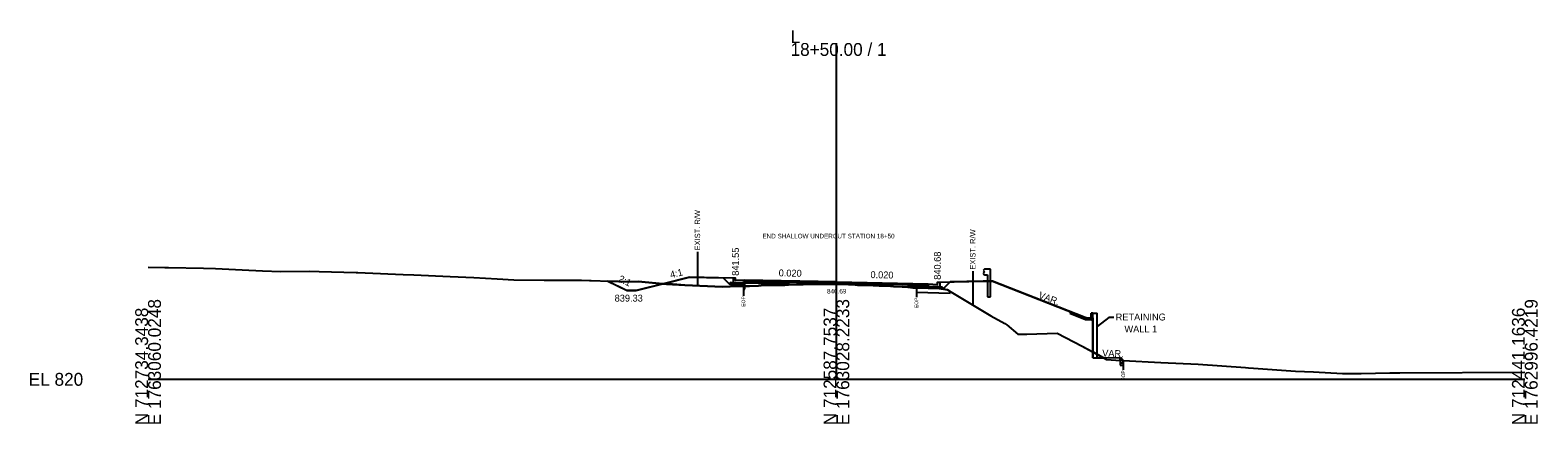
# Model space of a CAD drawing. Extents: x -26 to 5303, y -10 to 9578.
# Drawn here: x -25.7 to 302.8, y 8490.3 to 8576 of the extents above; entities that cross this region are included whole.
import ezdxf

# ---------------------------------------------------------------- set-up
doc = ezdxf.new("R2010")
doc.units = 0
for name, color, linetype in [('Default', 7, 'Continuous'), ('Exist CMT Pavement', 7, 'Continuous'), ('Exist Cross Section Cell', 7, 'Continuous'), ('Exist XS Ground Line', 7, 'Continuous'), ('Old_Level_10', 7, 'Continuous'), ('Old_Level_3', 7, 'Continuous'), ('Old_Level_4', 7, 'Continuous'), ('Prop CMT Conc Surface', 7, 'Continuous'), ('Prop CMT Concrete Structures', 7, 'Continuous'), ('Prop CMT Guardrail Graphics', 7, 'Continuous'), ('Prop CMT Pvmt Course 1', 7, 'Continuous'), ('Prop CMT Pvmt Course 1 CG', 7, 'Continuous'), ('Prop CMT Pvmt Course 2', 7, 'Continuous'), ('Prop CMT Pvmt Course 3', 7, 'Continuous'), ('Prop CMT Pvmt Surface', 7, 'Continuous'), ('Prop CMT Slope Grass', 7, 'Continuous'), ('Prop CMT Subgrade Earthwork', 7, 'Continuous'), ('Prop Retaining Wall', 7, 'Continuous'), ('Prop Shade Light', 7, 'Continuous'), ('Prop XS DDE', 7, 'Continuous'), ('Prop XS DDE Earthwork Shape', 7, 'Continuous'), ('Prop XS Earthwork Shape', 7, 'Continuous'), ('Prop XS Hydro Elevations', 7, 'Continuous'), ('Prop XS Hydro Slope Text', 7, 'Continuous'), ('Prop XS SBG', 7, 'Continuous'), ('Prop XS SE Text', 7, 'Continuous'), ('Prop XS Side Slope Text', 7, 'Continuous'), ('Prop XS Wedging', 7, 'Continuous'), ('Typical Curb CELL', 7, 'Continuous')]:
    doc.layers.add(name, color=color, linetype=linetype)

msp = doc.modelspace()

# ---------------------------------------------------------------- linework, layer by layer
at = {"layer": 'Exist CMT Pavement'}
msp.add_lwpolyline([(130, 8520.26), (130.74, 8520.3), (131.07, 8520.32), (133.05, 8520.39), (133.63, 8520.41), (135.72, 8520.48), (136.32, 8520.5), (138.75, 8520.54), (139.59, 8520.57), (141.31, 8520.62), (142.04, 8520.65), (142.78, 8520.67), (143.65, 8520.71), (144.12, 8520.72), (144.91, 8520.74), (145.38, 8520.73), (146.42, 8520.75), (147.52, 8520.73), (148.98, 8520.7), (149.39, 8520.69), (150, 8520.69), (151.54, 8520.69), (152.92, 8520.63), (154.1, 8520.56), (154.59, 8520.53), (155.22, 8520.51), (155.73, 8520.51), (156.15, 8520.48), (156.65, 8520.47), (159.31, 8520.38), (161.77, 8520.27), (162.45, 8520.23), (164.33, 8520.15), (165.54, 8520.06), (166.15, 8520.02), (166.63, 8519.96), (167.42, 8519.95)], dxfattribs=at)
at = {"layer": 'Exist Cross Section Cell'}
for p, q in [((150, 8500), (150, 8573.24)), ((0, 8500), (150, 8500)), ((150, 8500), (300, 8500))]:
    msp.add_line(p, q, dxfattribs=at)
at = {"layer": 'Exist XS Ground Line'}
msp.add_lwpolyline([(0, 8524.41), (3.67, 8524.36), (4.44, 8524.36), (12.08, 8524.19), (14.68, 8524.11), (20.49, 8523.81), (24.91, 8523.62), (28.9, 8523.49), (35.14, 8523.52), (37.31, 8523.45), (45.38, 8523.26), (45.72, 8523.25), (47.28, 8523.22), (55.61, 8522.86), (57.91, 8522.76), (65.84, 8522.39), (70.98, 8522.2), (76.07, 8521.92), (79.71, 8521.68), (86.34, 8521.62), (94.45, 8521.57), (96.17, 8521.54), (96.54, 8521.53), (104.57, 8521.26), (106.77, 8521.27), (112.98, 8520.7), (117, 8520.5), (121.9, 8520.28), (125.13, 8520.15), (128.64, 8520.28), (129.73, 8520.25), (130.74, 8520.3), (131.07, 8520.32), (131.9, 8520.35), (133.63, 8520.41), (135.72, 8520.48), (136.32, 8520.5), (138.75, 8520.54), (139.59, 8520.57), (141.31, 8520.62), (141.91, 8520.65), (142.72, 8520.67), (143.65, 8520.71), (144.15, 8520.72), (144.91, 8520.74), (145.38, 8520.73), (146.42, 8520.75), (147.52, 8520.73), (148.98, 8520.7), (149.39, 8520.69), (150, 8520.69), (151.54, 8520.69), (152.65, 8520.63), (154.21, 8520.58), (155.32, 8520.53), (155.73, 8520.51), (156.15, 8520.48), (156.65, 8520.47), (159.31, 8520.38), (161.77, 8520.27), (162.45, 8520.23), (164.33, 8520.15), (165.54, 8520.06), (166.15, 8520.02), (166.63, 8519.96), (167.42, 8519.95), (167.89, 8520.03), (172.4, 8519.75), (174.22, 8519.46), (183.62, 8513.84), (186.73, 8512.13), (187.14, 8511.86), (189.53, 8509.84), (191.51, 8509.87), (198.12, 8510.02), (203.57, 8507.24), (208.87, 8504.32), (210.86, 8504.17), (212.51, 8504.1), (220.69, 8503.69), (228.8, 8503.3), (239.16, 8502.54), (239.79, 8502.48), (240.86, 8502.41), (250.03, 8501.76), (253.93, 8501.61), (260.26, 8501.28), (263.46, 8501.3), (264.34, 8501.29), (270.62, 8501.44), (272.74, 8501.44), (300, 8501.53)], dxfattribs=at)
at = {"layer": 'Old_Level_10'}
for p, q in [((119.71, 8527.78), (119.71, 8520.38)), ((179.71, 8523.58), (179.71, 8516.18)), ((129.73, 8520.25), (129.73, 8518.2)), ((167.42, 8519.95), (167.42, 8517.9)), ((212.51, 8504.1), (212.51, 8502.05))]:
    msp.add_line(p, q, dxfattribs=at)
at = {"layer": 'Prop CMT Conc Surface'}
for points in [[(128, 8521.55), (128, 8522.05), (127.5, 8522.05)], [(130, 8521.59), (128, 8521.55)], [(170, 8520.8), (172, 8520.68)], [(172, 8520.68), (172, 8521.18), (172.5, 8521.18)]]:
    msp.add_lwpolyline(points, dxfattribs=at)
at = {"layer": 'Prop CMT Concrete Structures'}
for points in [[(130, 8521.59), (128, 8521.55), (128, 8522.05), (127.5, 8522.05)], [(127.5, 8522.05), (127.5, 8521.05), (130, 8521.01)], [(130, 8521.01), (130, 8521.59)], [(170, 8520.8), (172, 8520.68), (172, 8521.18), (172.5, 8521.18)], [(172.5, 8521.18), (172.5, 8520.16), (170, 8520.21)], [(170, 8520.21), (170, 8520.8)]]:
    msp.add_lwpolyline(points, dxfattribs=at)
at = {"layer": 'Prop CMT Guardrail Graphics'}
for points in [[(183.6, 8523.96), (182.27, 8523.96), (182, 8523.67)], [(182, 8523.67), (182.27, 8523.38)], [(182.27, 8523.38), (182, 8523.09)], [(182, 8523.09), (182.27, 8522.79), (182.94, 8522.79)], [(182.94, 8522.79), (182.94, 8517.96)], [(183.6, 8517.96), (183.6, 8523.96)], [(182.94, 8517.96), (183.6, 8517.96)]]:
    msp.add_lwpolyline(points, dxfattribs=at)
at = {"layer": 'Prop CMT Pvmt Course 1'}
for points in [[(130, 8521.34), (129.73, 8521.34)], [(129.73, 8521.34), (129.73, 8521.34)], [(129.73, 8521.34), (150, 8520.95)], [(150, 8521.2), (130, 8521.59)], [(130, 8521.59), (130, 8521.34)], [(150, 8520.95), (150, 8521.2)], [(150, 8521.2), (170, 8520.8)], [(150, 8520.95), (150, 8520.95), (150, 8520.95)], [(167.42, 8520.6), (150, 8520.95)], [(170, 8520.55), (167.42, 8520.6)], [(167.42, 8520.6), (167.42, 8520.6)], [(170, 8520.8), (170, 8520.55)]]:
    msp.add_lwpolyline(points, dxfattribs=at)
at = {"layer": 'Prop CMT Pvmt Course 1 CG'}
for points in [[(130, 8521.01), (127, 8521.06), (126.67, 8520.74)], [(126.67, 8520.74), (130, 8520.67)], [(130, 8520.67), (130, 8521.01)], [(170, 8520.21), (173, 8520.15), (173.34, 8519.81)], [(170, 8519.88), (170, 8520.21)], [(173.34, 8519.81), (170, 8519.88)]]:
    msp.add_lwpolyline(points, dxfattribs=at)
at = {"layer": 'Prop CMT Pvmt Course 2'}
for points in [[(129.73, 8521.01), (129.73, 8521.34)], [(129.73, 8521.34), (130, 8521.34)], [(130, 8521.01), (129.73, 8521.01)], [(130, 8521.34), (130, 8521.01)], [(167.42, 8520.26), (167.42, 8520.6)], [(167.42, 8520.6), (170, 8520.55)], [(170, 8520.21), (167.42, 8520.26)], [(170, 8520.55), (170, 8520.21)]]:
    msp.add_lwpolyline(points, dxfattribs=at)
at = {"layer": 'Prop CMT Pvmt Course 3'}
for points in [[(129.73, 8521.01), (130, 8521.01)], [(129.73, 8520.68), (129.73, 8521.01)], [(130, 8520.67), (129.73, 8520.68)], [(130, 8521.01), (130, 8520.67)], [(167.42, 8520.26), (170, 8520.21)], [(167.42, 8519.93), (167.42, 8520.26)], [(170, 8519.88), (167.42, 8519.93)], [(170, 8520.21), (170, 8519.88)]]:
    msp.add_lwpolyline(points, dxfattribs=at)
at = {"layer": 'Prop CMT Pvmt Surface'}
for points in [[(150, 8521.2), (130, 8521.59)], [(150, 8521.2), (170, 8520.8)]]:
    msp.add_lwpolyline(points, dxfattribs=at)
at = {"layer": 'Prop CMT Slope Grass'}
for p, q in [((184, 8521.41), (204.34, 8513.39)), ((204.34, 8513.39), (205.84, 8513.39)), ((205.84, 8513.39), (205.84, 8504.7)), ((205.84, 8504.7), (206.84, 8504.7)), ((211.84, 8504.6), (206.84, 8504.7)), ((211.84, 8504.6), (211.84, 8503.6)), ((211.84, 8503.6), (212.51, 8503.6)), ((212.51, 8503.6), (212.51, 8504.1))]:
    msp.add_line(p, q, dxfattribs=at)
for points in [[(127.5, 8522.05), (118, 8522.24), (112.55, 8520.88)], [(172.5, 8521.18), (182, 8521.37)], [(182, 8521.37), (184, 8521.41)], [(182, 8521.37), (184, 8521.41)]]:
    msp.add_lwpolyline(points, dxfattribs=at)
at = {"layer": 'Prop CMT Subgrade Earthwork'}
for p, q in [((130, 8520.67), (130, 8520.26)), ((167.42, 8519.95), (167.42, 8519.93))]:
    msp.add_line(p, q, dxfattribs=at)
for points in [[(130, 8520.67), (126.67, 8520.74), (125.32, 8522.09)], [(129.73, 8520.68), (130, 8520.67)], [(167.42, 8519.93), (170, 8519.88)], [(170, 8519.88), (173.34, 8519.81), (174.75, 8521.22)]]:
    msp.add_lwpolyline(points, dxfattribs=at)
at = {"layer": 'Prop Retaining Wall'}
for p, q in [((205.84, 8504.7), (205.84, 8514.39)), ((205.84, 8514.39), (206.84, 8514.39)), ((206.84, 8504.7), (206.84, 8514.39)), ((205.84, 8504.7), (206.84, 8504.7))]:
    msp.add_line(p, q, dxfattribs=at)
at = {"layer": 'Prop Shade Light'}
for p, q in [((129.73, 8520.25), (129.73, 8519.65)), ((129.73, 8519.65), (130.01, 8519.65)), ((130.01, 8519.65), (130.01, 8520.26)), ((170, 8519.88), (167.42, 8519.93)), ((167.42, 8519.93), (167.42, 8518.97)), ((167.42, 8518.97), (174.77, 8518.77)), ((170.57, 8519.87), (170, 8519.88)), ((174.76, 8519.13), (174.22, 8519.46)), ((174.77, 8518.77), (174.76, 8519.13))]:
    msp.add_line(p, q, dxfattribs=at)
for points in [[(130.01, 8520.26), (130, 8520.26), (129.73, 8520.25)], [(174.22, 8519.46), (172.4, 8519.75), (170.57, 8519.87)]]:
    msp.add_lwpolyline(points, dxfattribs=at)
at = {"layer": 'Prop XS DDE'}
for p, q in [((100.14, 8521.44), (104.37, 8519.33)), ((106.37, 8519.33), (104.37, 8519.33)), ((112.55, 8520.88), (106.37, 8519.33))]:
    msp.add_line(p, q, dxfattribs=at)
at = {"layer": 'Prop XS DDE Earthwork Shape'}
for p, q in [((100.22, 8521.4), (104.37, 8519.33)), ((104.37, 8519.33), (106.37, 8519.33)), ((106.37, 8519.33), (112.15, 8520.77)), ((112.15, 8520.77), (106.77, 8521.27))]:
    msp.add_line(p, q, dxfattribs=at)
msp.add_lwpolyline([(106.77, 8521.27), (104.57, 8521.26), (100.22, 8521.4)], dxfattribs=at)
at = {"layer": 'Prop XS Earthwork Shape'}
for points in [[(130, 8520.67), (130, 8520.26), (129.73, 8520.25), (128.64, 8520.28), (125.13, 8520.15), (121.9, 8520.28), (117, 8520.5), (112.55, 8520.88), (118, 8522.24), (125.32, 8522.09), (126.67, 8520.74), (129.73, 8520.68)], [(167.42, 8519.95), (167.42, 8519.93), (170, 8519.88), (170.57, 8519.87), (167.89, 8520.03)], [(187.14, 8511.86), (189.53, 8509.84), (191.51, 8509.87), (198.12, 8510.02), (203.57, 8507.24), (205.84, 8505.99), (205.84, 8512.8), (184, 8521.41), (182, 8521.37), (174.75, 8521.22), (173.34, 8519.81), (170.57, 8519.87), (172.4, 8519.75), (174.22, 8519.46), (183.62, 8513.84), (186.73, 8512.13)], [(186.73, 8512.13), (187.14, 8511.86), (189.53, 8509.84), (191.51, 8509.87), (198.12, 8510.02), (203.57, 8507.24), (205.84, 8505.99), (205.84, 8512.8), (184, 8521.41), (182, 8521.37), (174.75, 8521.22), (173.34, 8519.81), (170.57, 8519.87), (172.4, 8519.75), (174.22, 8519.46), (183.62, 8513.84)], [(205.84, 8504.7), (206.84, 8504.7), (208.22, 8504.68), (205.84, 8505.99)], [(210.86, 8504.17), (211.84, 8504.13), (211.84, 8504.6), (208.22, 8504.68), (208.87, 8504.32)], [(211.84, 8503.6), (212.51, 8503.6), (212.51, 8504.1), (211.84, 8504.13)]]:
    msp.add_lwpolyline(points, close=True, dxfattribs=at)
at = {"layer": 'Prop XS SBG'}
for p, q in [((201.02, 8514.7), (200.89, 8514.39)), ((200.89, 8514.39), (204.28, 8513.06)), ((204.28, 8513.06), (205.84, 8513.06)), ((205.51, 8513.39), (205.51, 8514.39)), ((205.84, 8514.39), (205.51, 8514.39))]:
    msp.add_line(p, q, dxfattribs=at)
at = {"layer": 'Prop XS Side Slope Text'}
for p, q in [((209.36, 8513.5), (206.84, 8511.53)), ((210.47, 8513.5), (209.36, 8513.5))]:
    msp.add_line(p, q, dxfattribs=at)
at = {"layer": 'Prop XS Wedging'}
for points in [[(130, 8520.26), (130, 8521.34), (130.74, 8521.32), (131.07, 8521.32), (133.05, 8521.28), (133.63, 8521.27), (135.72, 8521.23), (136.32, 8521.21), (138.75, 8521.17), (139.59, 8521.15), (141.31, 8521.12), (142.04, 8521.1), (142.78, 8521.09), (143.65, 8521.07), (144.12, 8521.06), (144.91, 8521.05), (145.38, 8521.04), (146.42, 8521.02), (147.52, 8520.99), (148.98, 8520.97), (149.39, 8520.96), (150, 8520.95), (151.54, 8520.92), (152.92, 8520.89), (154.1, 8520.86), (154.59, 8520.85), (155.22, 8520.84), (155.73, 8520.83), (156.15, 8520.82), (156.65, 8520.81), (159.31, 8520.76), (161.77, 8520.71), (162.45, 8520.7), (164.33, 8520.66), (165.54, 8520.64), (166.15, 8520.62), (166.63, 8520.61), (167.42, 8520.6), (167.42, 8519.95), (166.63, 8519.96), (166.15, 8520.02), (165.54, 8520.06), (164.33, 8520.15), (162.45, 8520.24), (161.77, 8520.27), (159.31, 8520.38), (156.65, 8520.47), (156.15, 8520.48), (155.73, 8520.51), (155.22, 8520.51), (154.59, 8520.53), (154.1, 8520.56), (152.92, 8520.63), (151.54, 8520.69), (150, 8520.69), (149.39, 8520.69), (148.98, 8520.7), (147.52, 8520.73), (146.42, 8520.75), (145.38, 8520.73), (144.91, 8520.74), (144.12, 8520.72), (143.65, 8520.71), (142.78, 8520.67), (142.04, 8520.65), (141.31, 8520.62), (139.59, 8520.57), (138.75, 8520.54), (136.32, 8520.5), (135.72, 8520.48), (133.63, 8520.41), (133.05, 8520.39), (131.07, 8520.32), (130.74, 8520.3)], [(130, 8520.26), (130, 8521.01), (130.74, 8520.99), (131.07, 8520.99), (133.05, 8520.95), (133.63, 8520.94), (135.72, 8520.9), (136.32, 8520.88), (138.75, 8520.84), (139.59, 8520.82), (139.62, 8520.82), (139.86, 8520.58), (139.59, 8520.57), (138.75, 8520.54), (136.32, 8520.5), (135.72, 8520.48), (133.63, 8520.41), (133.05, 8520.39), (131.07, 8520.32), (130.74, 8520.3)], [(165.41, 8520.07), (165.65, 8520.3), (166.15, 8520.29), (166.63, 8520.28), (167.42, 8520.27), (167.42, 8519.95), (166.63, 8519.96), (166.15, 8520.02), (165.54, 8520.06)]]:
    msp.add_lwpolyline(points, close=True, dxfattribs=at)
at = {"layer": 'Typical Curb CELL'}
for p, q in [((211.84, 8504.6), (212.03, 8504.6)), ((211.84, 8504.6), (211.84, 8503.6)), ((211.84, 8503.61), (211.84, 8503.1)), ((211.84, 8503.6), (212.51, 8503.6)), ((211.84, 8503.1), (212.51, 8503.1)), ((212.51, 8504.19), (212.15, 8504.55)), ((212.51, 8504.19), (212.51, 8503.6)), ((212.51, 8503.61), (212.51, 8503.1))]:
    msp.add_line(p, q, dxfattribs=at)
msp.add_arc((212.03, 8504.44), 0.167, 43.9997, 90, dxfattribs=at)

# ---------------------------------------------------------------- texts
at = {"layer": 'Default'}
msp.add_text('-', height=0.0001, dxfattribs=at).set_placement((0, 8500))
at = {"layer": 'Exist Cross Section Cell'}
for s, p in [('L', (140, 8573.24)), ('18+50.00 / 1', (140, 8570.44)), ('EL 820', (-26, 8498.6))]:
    msp.add_text(s, height=2.8, dxfattribs=at).set_placement(p)
for s, p in [('E 1763060.0248', (2.8, 8490)), ('E 1763028.2233', (152.8, 8490)), ('E 1762996.4219', (302.8, 8490)), ('N 712734.3438', (0, 8490)), ('N 712587.7537', (150, 8490)), ('N 712441.1636', (300, 8490))]:
    msp.add_text(s, height=2.8, rotation=90, dxfattribs=at).set_placement(p)
at = {"layer": 'Old_Level_10'}
for s, height, p in [('EXIST. R/W', 1.181, (120.3, 8528.08)), ('EXIST. R/W', 1.181, (180.3, 8523.88)), ('EOP', 0.787, (130.12, 8515.8)), ('EOP', 0.787, (167.82, 8515.51)), ('EOP', 0.787, (212.9, 8499.66))]:
    msp.add_text(s, height=height, rotation=90, dxfattribs=at).set_placement(p)
at = {"layer": 'Old_Level_3'}
msp.add_text('840.69', height=1, dxfattribs=at).set_placement((147.95, 8518.69))
at = {"layer": 'Old_Level_4'}
msp.add_text('END SHALLOW UNDERCUT STATION 18+50', height=1, dxfattribs=at).set_placement((133.87, 8530.7))
at = {"layer": 'Prop XS Hydro Elevations'}
for s, p in [('841.55', (128.75, 8522.55)), ('840.68', (172.75, 8521.68))]:
    msp.add_text(s, height=1.5, rotation=90, dxfattribs=at).set_placement(p)
at = {"layer": 'Prop XS Hydro Slope Text'}
msp.add_text('2:1', height=1.5, rotation=333.4349, dxfattribs=at).set_placement((102.32, 8521.42))
msp.add_text('839.33', height=1.5, dxfattribs=at).set_placement((101.67, 8516.93))
at = {"layer": 'Prop XS SE Text'}
for rotation, p in [(358.8745, (137.4, 8522.44)), (358.8542, (157.4, 8522.05))]:
    msp.add_text('0.020', height=1.5, rotation=rotation, dxfattribs=at).set_placement(p)
at = {"layer": 'Prop XS Side Slope Text'}
for s, rotation, p in [('4:1', 14.0362, (113.94, 8522)), ('VAR.', 339.336, (193.9, 8517.75)), ('RETAINING ', 360, (210.85, 8512.82)), ('WALL 1', 360, (212.76, 8510.2)), ('VAR.', 357.7795, (207.89, 8504.98))]:
    msp.add_text(s, height=1.5, rotation=rotation, dxfattribs=at).set_placement(p)

doc.saveas('drawing.dxf')
